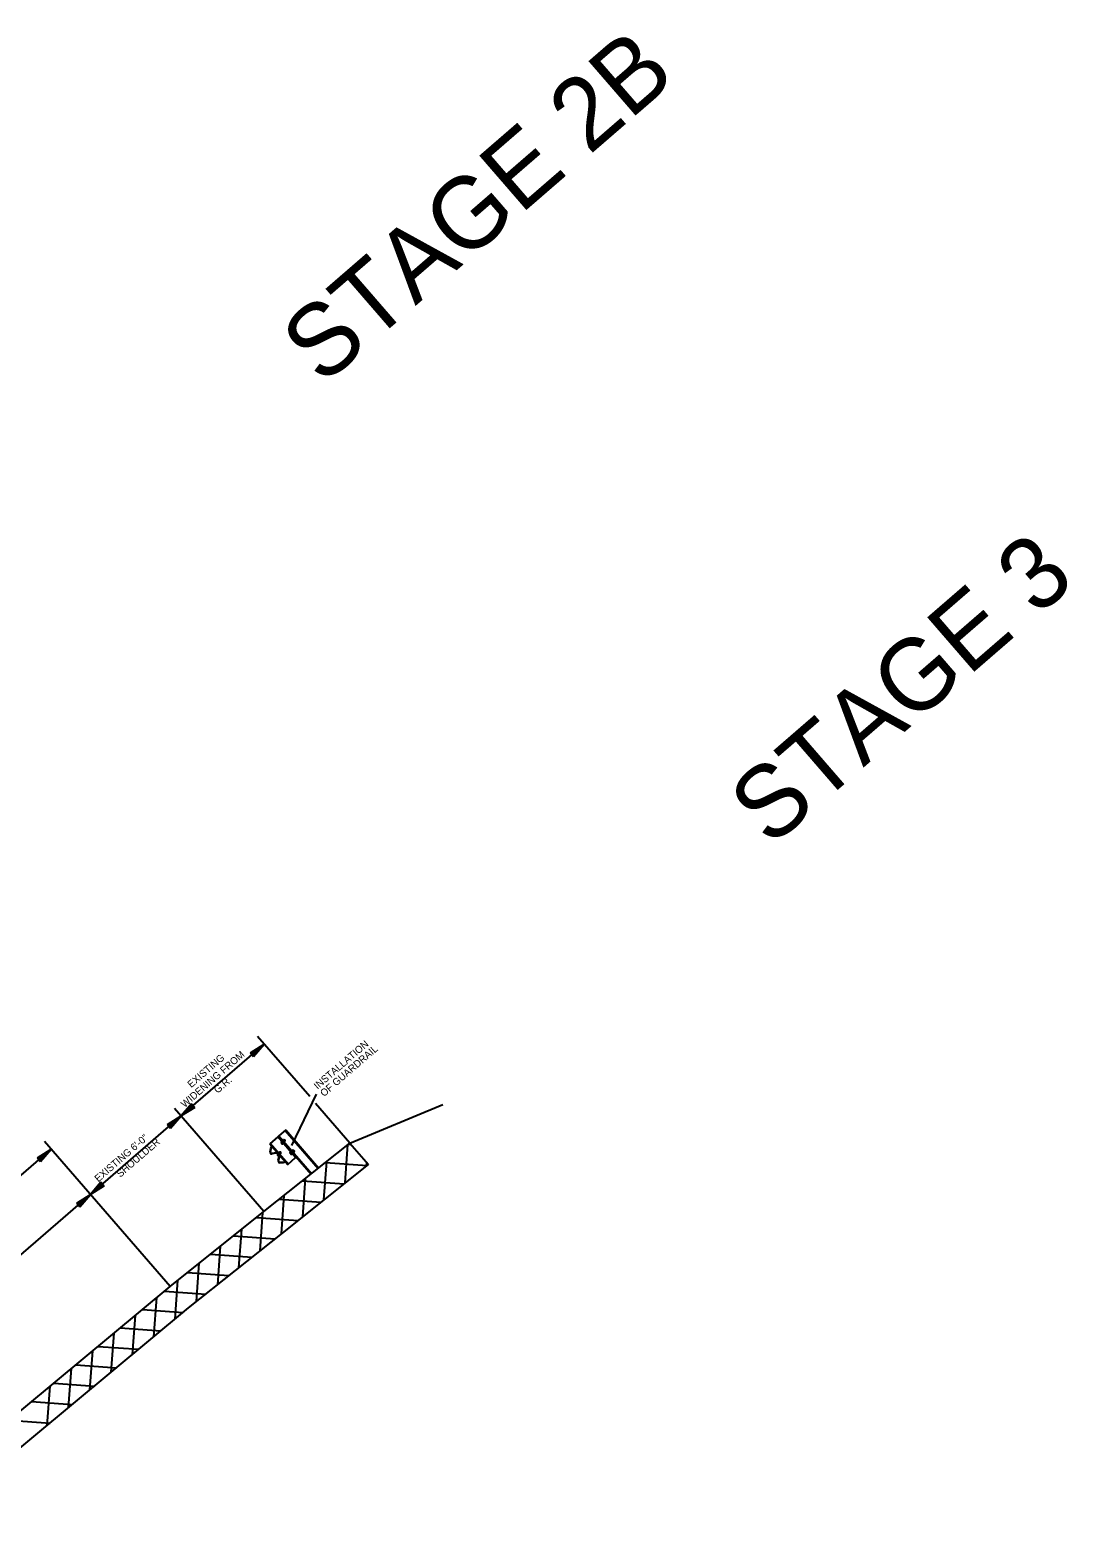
# Model space of a CAD drawing. Extents: x 192699 to 285914, y 194342 to 233219.
# Drawn here: x 262898 to 262949.9, y 213585.8 to 213661.2 of the extents above; entities that cross this region are included whole.
import ezdxf

# ---------------------------------------------------------------- set-up
doc = ezdxf.new("R2010")
doc.units = 0
doc.layers.add('TYPICAL SECTION FOR MOT', color=7, linetype='Continuous')

msp = doc.modelspace()

# ---------------------------------------------------------------- linework, layer by layer
at = {"layer": 'TYPICAL SECTION FOR MOT'}
for p, q in [((262911.971, 213607.843), (262909.365, 213610.853)), ((262905.534, 213606.875), (262909.692, 213610.474)), ((262909.009, 213610.042), (262909.692, 213610.474)), ((262909.009, 213610.042), (262909.166, 213609.86)), ((262909.022, 213610.026), (262909.591, 213610.387)), ((262909.035, 213610.011), (262909.487, 213610.297)), ((262909.049, 213609.996), (262909.387, 213610.21)), ((262909.062, 213609.98), (262909.284, 213610.121)), ((262909.075, 213609.965), (262909.183, 213610.034)), ((262909.1, 213609.937), (262909.183, 213610.034)), ((262909.113, 213609.921), (262909.284, 213610.121)), ((262909.127, 213609.906), (262909.387, 213610.21)), ((262909.14, 213609.891), (262909.487, 213610.297)), ((262909.153, 213609.875), (262909.591, 213610.387)), ((262909.166, 213609.86), (262909.692, 213610.474)), ((262912.288, 213607.973), (262911.059, 213605.395)), ((262909.678, 213602.088), (262905.207, 213607.253)), ((262906.06, 213607.489), (262905.534, 213606.875)), ((262906.218, 213607.308), (262905.534, 213606.875)), ((262906.074, 213607.474), (262905.635, 213606.962)), ((262906.204, 213607.323), (262905.635, 213606.962)), ((262906.087, 213607.458), (262905.739, 213607.052)), ((262906.191, 213607.338), (262905.739, 213607.052)), ((262906.1, 213607.443), (262905.84, 213607.139)), ((262906.178, 213607.353), (262905.84, 213607.139)), ((262906.113, 213607.428), (262905.942, 213607.228)), ((262906.164, 213607.369), (262905.942, 213607.228)), ((262906.127, 213607.412), (262906.043, 213607.316)), ((262906.151, 213607.384), (262906.043, 213607.316)), ((262906.218, 213607.308), (262906.06, 213607.489)), ((262913.98, 213605.521), (262912.264, 213607.504)), ((262913.98, 213605.521), (262918.635, 213607.445)), ((262900.998, 213602.948), (262905.534, 213606.875)), ((262904.851, 213606.442), (262905.534, 213606.875)), ((262904.851, 213606.442), (262905.008, 213606.26)), ((262904.864, 213606.427), (262905.433, 213606.787)), ((262904.877, 213606.411), (262905.329, 213606.697)), ((262904.89, 213606.396), (262905.228, 213606.61)), ((262904.904, 213606.38), (262905.126, 213606.521)), ((262904.917, 213606.365), (262905.025, 213606.434)), ((262904.942, 213606.337), (262905.025, 213606.434)), ((262904.955, 213606.321), (262905.126, 213606.521)), ((262904.968, 213606.306), (262905.228, 213606.61)), ((262904.981, 213606.291), (262905.329, 213606.697)), ((262904.995, 213606.275), (262905.433, 213606.787)), ((262905.008, 213606.26), (262905.534, 213606.875)), ((262904.985, 213598.342), (262898.707, 213605.594)), ((262909.678, 213602.088), (262913.98, 213605.521)), ((262910.371, 213605.832), (262910.426, 213605.875)), ((262910.371, 213605.832), (262910.376, 213605.836)), ((262912.045, 213603.951), (262910.397, 213605.855)), ((262910.568, 213605.595), (262910.531, 213605.563)), ((262910.531, 213605.563), (262910.612, 213605.468)), ((262910.573, 213605.516), (262910.615, 213605.552)), ((262910.623, 213605.649), (262910.659, 213605.68)), ((262910.704, 213605.555), (262910.623, 213605.649)), ((262910.642, 213605.626), (262910.679, 213605.658)), ((262910.736, 213605.603), (262910.674, 213605.674)), ((262910.684, 213605.578), (262910.721, 213605.61)), ((262910.684, 213605.578), (262910.717, 213605.606)), ((262910.704, 213605.555), (262910.742, 213605.587)), ((262910.747, 213606.155), (262912.393, 213604.253)), ((262910.77, 213606.174), (262912.416, 213604.273)), ((262913.98, 213605.521), (262914.908, 213604.45)), ((262887.694, 213595.398), (262899.034, 213605.216)), ((262898.351, 213604.783), (262899.034, 213605.216)), ((262898.351, 213604.783), (262898.508, 213604.601)), ((262898.364, 213604.768), (262898.933, 213605.128)), ((262898.377, 213604.752), (262898.829, 213605.038)), ((262898.39, 213604.737), (262898.729, 213604.951)), ((262898.404, 213604.721), (262898.626, 213604.862)), ((262898.417, 213604.706), (262898.525, 213604.775)), ((262898.442, 213604.678), (262898.525, 213604.775)), ((262898.455, 213604.662), (262898.626, 213604.862)), ((262898.468, 213604.647), (262898.729, 213604.951)), ((262898.482, 213604.632), (262898.829, 213605.038)), ((262898.495, 213604.616), (262898.933, 213605.128)), ((262898.508, 213604.601), (262899.034, 213605.216)), ((262909.996, 213605.084), (262910.027, 213605.248)), ((262910.89, 213604.471), (262909.999, 213605.5)), ((262910.017, 213605.081), (262910.047, 213605.245)), ((262910.027, 213605.248), (262910.072, 213605.367)), ((262910.047, 213605.245), (262910.085, 213605.343)), ((262910.288, 213605.035), (262910.089, 213605.002)), ((262910.292, 213605.011), (262910.093, 213604.978)), ((262910.437, 213604.898), (262910.349, 213604.997)), ((262910.454, 213604.915), (262910.367, 213605.012)), ((262910.396, 213604.663), (262910.449, 213604.837)), ((262910.412, 213605.042), (262910.449, 213605.074)), ((262910.494, 213604.948), (262910.412, 213605.042)), ((262910.418, 213604.656), (262910.472, 213604.83)), ((262910.433, 213605.019), (262910.47, 213605.051)), ((262910.526, 213604.995), (262910.464, 213605.067)), ((262910.475, 213604.971), (262910.512, 213605.003)), ((262910.475, 213604.971), (262910.507, 213604.999)), ((262910.494, 213604.948), (262910.532, 213604.981)), ((262910.65, 213605.501), (262910.612, 213605.468)), ((262910.978, 213605.046), (262911.015, 213605.078)), ((262911.06, 213604.951), (262910.978, 213605.046)), ((262911.02, 213604.999), (262911.063, 213605.035)), ((262911.06, 213604.951), (262911.098, 213604.984)), ((262911.081, 213605.135), (262911.118, 213605.167)), ((262911.163, 213605.04), (262911.081, 213605.135)), ((262911.101, 213605.111), (262911.139, 213605.144)), ((262911.195, 213605.088), (262911.133, 213605.159)), ((262911.143, 213605.063), (262911.181, 213605.096)), ((262911.143, 213605.063), (262911.176, 213605.091)), ((262911.163, 213605.04), (262911.201, 213605.073)), ((262911.268, 213604.799), (262911.293, 213604.821)), ((262913.75, 213603.527), (262913.888, 213605.448)), ((262913.918, 213605.472), (262914.03, 213605.464)), ((262910.645, 213604.546), (262910.478, 213604.546)), ((262910.645, 213604.525), (262910.478, 213604.525)), ((262910.605, 213601.017), (262914.908, 213604.45)), ((262910.762, 213604.576), (262910.645, 213604.546)), ((262910.769, 213604.556), (262910.645, 213604.525)), ((262912.686, 213602.678), (262912.825, 213604.599)), ((262912.766, 213604.552), (262914.847, 213604.402)), ((262914.814, 213604.376), (262914.826, 213604.545)), ((262901.524, 213603.562), (262900.998, 213602.948)), ((262901.681, 213603.38), (262900.998, 213602.948)), ((262901.537, 213603.547), (262901.099, 213603.035)), ((262901.668, 213603.396), (262901.099, 213603.035)), ((262901.551, 213603.531), (262901.203, 213603.125)), ((262901.655, 213603.411), (262901.203, 213603.125)), ((262901.564, 213603.516), (262901.304, 213603.212)), ((262901.642, 213603.426), (262901.304, 213603.212)), ((262901.577, 213603.501), (262901.406, 213603.301)), ((262901.628, 213603.442), (262901.406, 213603.301)), ((262901.59, 213603.485), (262901.507, 213603.388)), ((262901.615, 213603.457), (262901.507, 213603.388)), ((262901.681, 213603.38), (262901.524, 213603.562)), ((262911.613, 213603.632), (262913.695, 213603.483)), ((262911.623, 213601.829), (262911.761, 213603.75)), ((262889.657, 213593.13), (262900.998, 213602.948)), ((262900.314, 213602.515), (262900.998, 213602.948)), ((262900.314, 213602.515), (262900.472, 213602.333)), ((262900.328, 213602.499), (262900.897, 213602.86)), ((262900.341, 213602.484), (262900.793, 213602.77)), ((262900.354, 213602.469), (262900.692, 213602.683)), ((262900.368, 213602.453), (262900.59, 213602.594)), ((262900.381, 213602.438), (262900.489, 213602.507)), ((262900.405, 213602.41), (262900.489, 213602.507)), ((262900.419, 213602.394), (262900.59, 213602.594)), ((262900.432, 213602.379), (262900.692, 213602.683)), ((262900.445, 213602.364), (262900.793, 213602.77)), ((262900.458, 213602.348), (262900.897, 213602.86)), ((262900.472, 213602.333), (262900.998, 213602.948)), ((262910.461, 213602.713), (262912.543, 213602.563)), ((262910.559, 213600.98), (262910.697, 213602.901)), ((262904.985, 213598.342), (262909.678, 213602.088)), ((262909.309, 213601.793), (262911.39, 213601.643)), ((262909.495, 213600.131), (262909.634, 213602.052)), ((262905.912, 213597.271), (262910.605, 213601.017)), ((262908.432, 213599.282), (262908.57, 213601.204)), ((262907.368, 213598.433), (262907.506, 213600.355)), ((262908.156, 213600.873), (262910.238, 213600.724)), ((262906.304, 213597.584), (262906.443, 213599.506)), ((262907.004, 213599.954), (262909.086, 213599.804)), ((262905.852, 213599.034), (262907.933, 213598.884)), ((262891.14, 213586.833), (262904.985, 213598.342)), ((262904.71, 213598.114), (262906.781, 213597.965)), ((262905.239, 213596.712), (262905.379, 213598.657)), ((262892.068, 213585.762), (262905.912, 213597.271)), ((262904.173, 213595.825), (262904.314, 213597.784)), ((262903.106, 213594.939), (262903.247, 213596.898)), ((262903.6, 213597.191), (262905.639, 213597.044)), ((262902.04, 213594.052), (262902.181, 213596.011)), ((262902.49, 213596.268), (262904.529, 213596.122)), ((262900.973, 213593.166), (262901.114, 213595.125)), ((262901.38, 213595.346), (262903.419, 213595.199)), ((262899.907, 213592.279), (262900.048, 213594.238)), ((262900.27, 213594.423), (262902.309, 213594.276)), ((262899.16, 213593.5), (262901.199, 213593.353)), ((262898.841, 213591.393), (262898.982, 213593.352)), ((262898.05, 213592.578), (262900.089, 213592.431)), ((262896.94, 213591.655), (262898.98, 213591.508))]:
    msp.add_line(p, q, dxfattribs=at)
for points in [[(262909.975, 213605.488), (262910.871, 213604.455), (262911.268, 213604.799), (262910.371, 213605.832)], [(262910.531, 213605.563), (262910.613, 213605.469), (262910.655, 213605.505), (262910.573, 213605.599)], [(262910.61, 213605.665), (262910.72, 213605.538), (262910.713, 213605.531), (262910.603, 213605.658)], [(262910.686, 213605.663), (262910.727, 213605.616), (262910.746, 213605.632), (262910.705, 213605.679)], [(262910.4, 213605.058), (262910.51, 213604.931), (262910.502, 213604.925), (262910.393, 213605.052)], [(262910.476, 213605.056), (262910.517, 213605.009), (262910.536, 213605.025), (262910.495, 213605.073)], [(262910.979, 213605.046), (262911.061, 213604.952), (262911.103, 213604.988), (262911.021, 213605.082)], [(262911.07, 213605.151), (262911.18, 213605.024), (262911.172, 213605.018), (262911.062, 213605.145)], [(262911.145, 213605.149), (262911.187, 213605.102), (262911.205, 213605.118), (262911.164, 213605.166)]]:
    msp.add_lwpolyline(points, close=True, dxfattribs=at)
msp.add_lwpolyline([(262910.77, 213606.174), (262910.426, 213605.875), (262912.073, 213603.975)], dxfattribs=at)
for centre, radius, start, end in [((262910.658, 213605.659), 0.022, 358.65889, 86.30885), ((262910.635, 213605.577), 0.0922, 20.62557, 61.14103), ((262910.717, 213605.585), 0.025, 4.25993, 79.94989), ((262910.076, 213605.063), 0.0856, 162.90505, 281.63339), ((262910.076, 213605.063), 0.062, 162.90505, 281.63339), ((262910.307, 213604.951), 0.0865, 45.83891, 102.77731), ((262910.307, 213604.951), 0.0622, 45.83891, 102.77731), ((262910.403, 213604.945), 0.0453, 134.81357, 297.92793), ((262910.408, 213604.861), 0.0462, 334.02966, 49.10286), ((262910.448, 213605.052), 0.022, 358.65889, 86.30885), ((262910.408, 213604.861), 0.0703, 334.02966, 49.10286), ((262910.425, 213604.97), 0.0922, 20.62557, 61.14103), ((262910.507, 213604.978), 0.025, 4.25993, 79.94989), ((262911.117, 213605.145), 0.022, 358.65889, 86.30885), ((262911.094, 213605.063), 0.0922, 20.62557, 61.14103), ((262911.176, 213605.071), 0.025, 4.25993, 79.94989), ((262910.499, 213604.629), 0.109, 161.76335, 255.66487), ((262910.499, 213604.629), 0.0854, 161.76335, 255.66487)]:
    msp.add_arc(centre, radius, start, end, dxfattribs=at)

# ---------------------------------------------------------------- texts
for s, height, p in [('STAGE 2B', 3.6, (262912.608, 213643.38)), ('STAGE 3', 3.6, (262935.025, 213620.274)), ('WIDENING FROM', 0.36, (262905.716, 213607.268)), ('INSTALLATION', 0.36, (262912.367, 213608.185)), ('OF GUARDRAIL', 0.36, (262912.687, 213607.818)), ('EXISTING', 0.36, (262906.044, 213608.266)), ('G.R.', 0.36, (262907.364, 213607.981)), ('EXISTING 6\'-0"', 0.36, (262901.394, 213603.545)), ('SHOULDER', 0.36, (262902.491, 213603.78))]:
    msp.add_text(s, height=height, rotation=40.8833, dxfattribs=at).set_placement(p)

doc.saveas('drawing.dxf')
